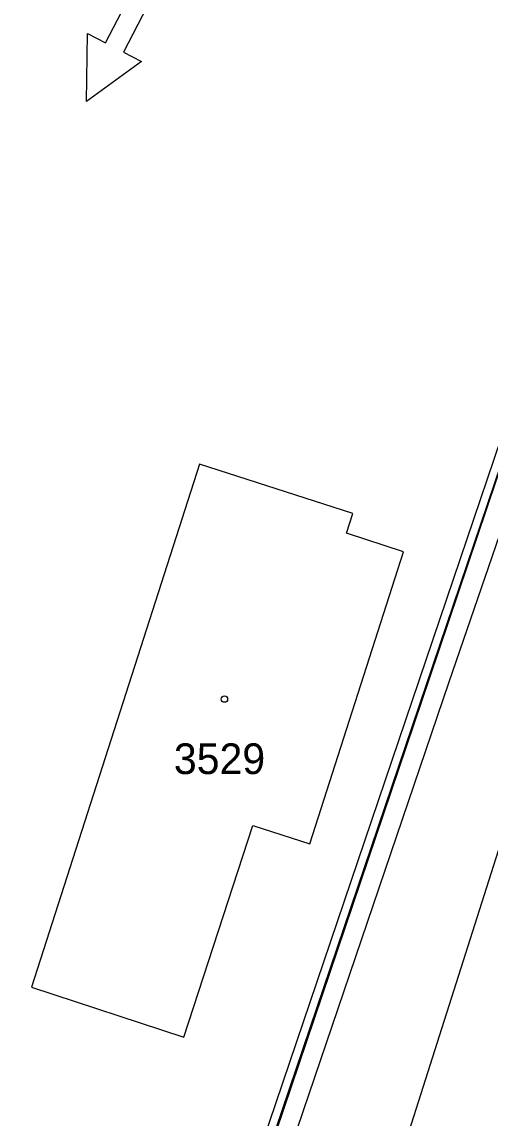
# Model space of a CAD drawing. Extents: x -781083 to -763634, y -1029516 to -1022695.
# Drawn here: x -765251.4 to -765225.5, y -1024274.3 to -1024213.6 of the extents above; entities that cross this region are included whole.
import ezdxf

# ---------------------------------------------------------------- set-up
doc = ezdxf.new("R2010")
doc.units = 0
for name, color, linetype in [('Hranice parcel', 7, 'Continuous'), ('Parcelní čísla', 7, 'Continuous'), ('směry', 7, 'Continuous'), ('Vnitřní kresba', 7, 'Continuous'), ('Vrstva 17', 7, 'Continuous'), ('Vrstva 51', 7, 'Continuous'), ('Značky budov', 7, 'Continuous')]:
    doc.layers.add(name, color=color, linetype=linetype)

# ---------------------------------------------------------------- blocks, each defined once
blk = doc.blocks.new('4.02')
at = {"layer": 'Značky budov'}
blk.add_circle((-0.07, 0.01), 1.75, dxfattribs=at)

msp = doc.modelspace()

# ---------------------------------------------------------------- linework, layer by layer
at = {"layer": 'Hranice parcel'}
for points in [[(-765213.08, -1024202.74), (-765218.18, -1024218.22), (-765219.59, -1024222.39), (-765251.79, -1024317.45)], [(-765235.49, -1024259.1), (-765230.3, -1024242.92), (-765233.46, -1024241.9), (-765233.1, -1024240.8), (-765241.6, -1024238.07), (-765250.9, -1024267.04), (-765242.46, -1024269.81), (-765238.65, -1024258.09), (-765235.49, -1024259.1)]]:
    msp.add_lwpolyline(points, dxfattribs=at)
at = {"layer": 'směry'}
msp.add_lwpolyline([(-765230.359, -1024185.393), (-765245.808, -1024215.246), (-765244.81, -1024215.762), (-765247.855, -1024217.981), (-765247.803, -1024214.214), (-765246.805, -1024214.73), (-765245.257, -1024211.737)], dxfattribs=at)
at = {"layer": 'Vnitřní kresba'}
msp.add_line((-765248.07, -1024305.05), (-765220.02, -1024222.25), dxfattribs=at)
at = {"layer": 'Vrstva 17'}
msp.add_lwpolyline([(-765247.548, -1024305.21), (-765228.844, -1024249.881), (-765210.873, -1024196.594), (-765192.521, -1024155.45), (-765183.275, -1024117.083), (-765178.507, -1024097.058)], dxfattribs=at)
at = {"layer": 'Vrstva 51'}
for points in [[(-765227.767, -1024250.123), (-765216.209, -1024216.525), (-765208.606, -1024196.975), (-765198.808, -1024179.343), (-765189.293, -1024169.604)], [(-765246.707, -1024306.022), (-765239.08, -1024283.456), (-765227.767, -1024250.123)], [(-765245.138, -1024322.793), (-765233.231, -1024285.247), (-765222.558, -1024251.694)]]:
    msp.add_lwpolyline(points, dxfattribs=at)

# ---------------------------------------------------------------- block references
at = {"layer": 'Značky budov', "xscale": 0.1, "yscale": 0.10000000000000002}
msp.add_blockref('4.02', (-765240.21, -1024251.09), dxfattribs=at)

# ---------------------------------------------------------------- texts
at = {"layer": 'Parcelní čísla'}
msp.add_text('3529', height=1.7, dxfattribs=at).set_placement((-765243.02, -1024255.24))

doc.saveas('drawing.dxf')
